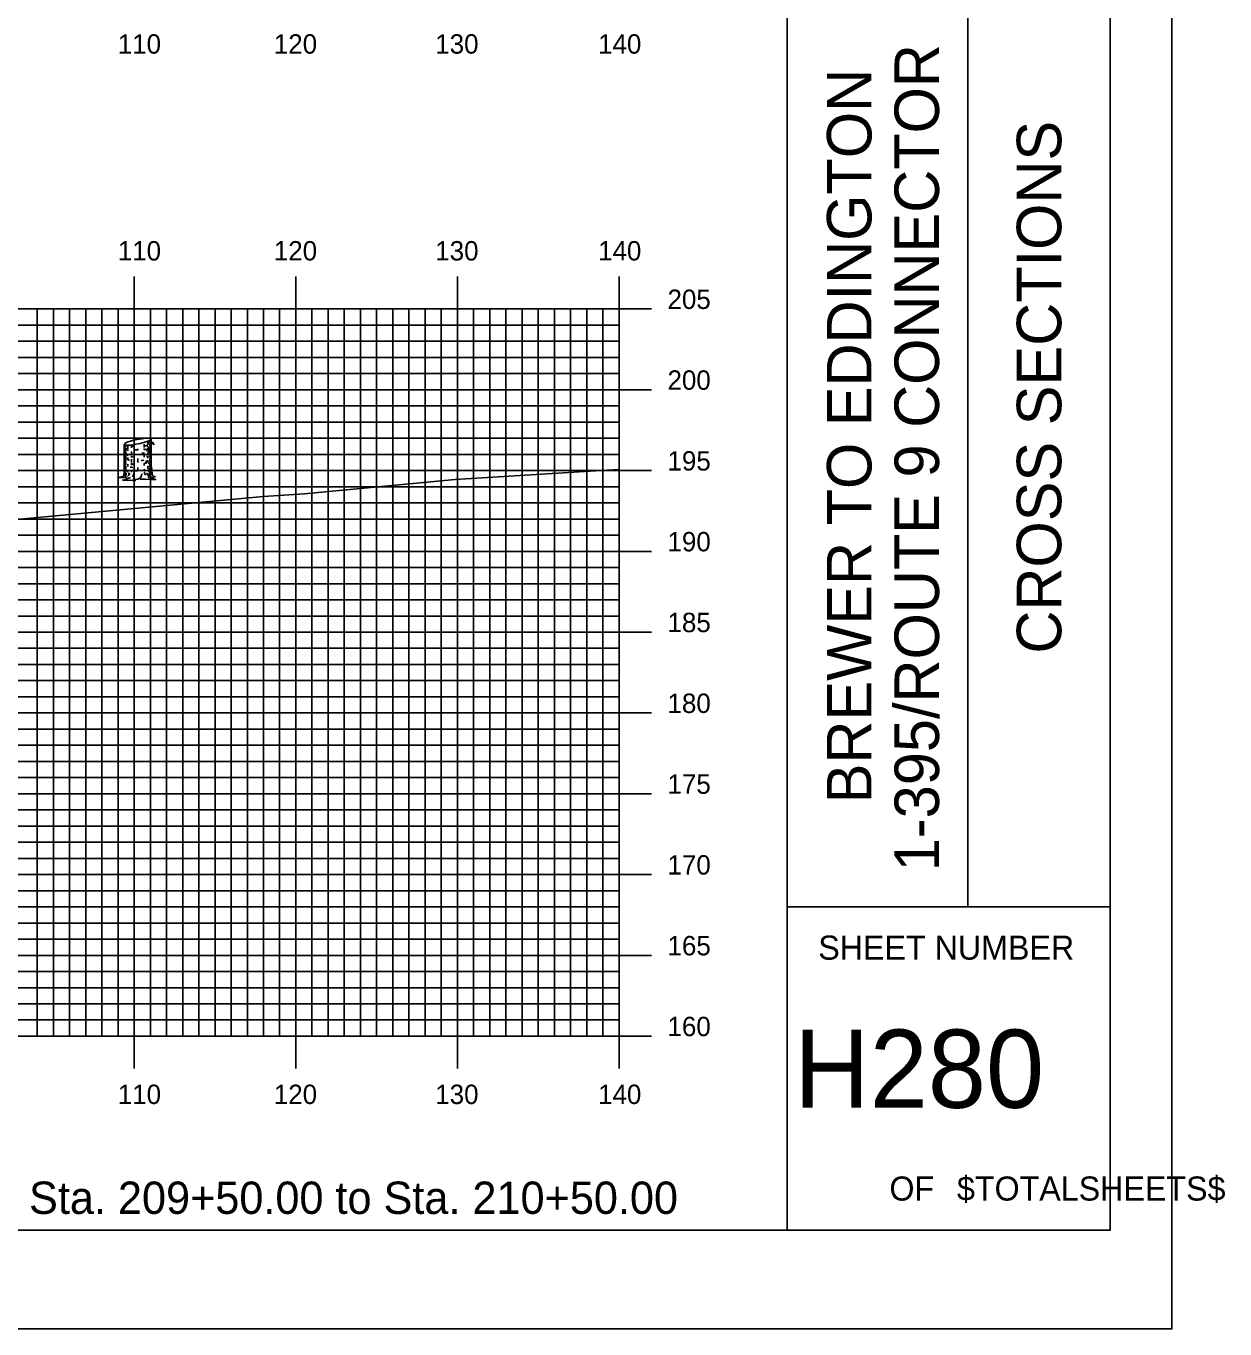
# Model space of a CAD drawing. Extents: x 1794453 to 1794796, y 442591 to 442811.
# Drawn here: x 1794721.6 to 1794795.8, y 442590.5 to 442671.2 of the extents above; entities that cross this region are included whole.
import ezdxf

# ---------------------------------------------------------------- set-up
doc = ezdxf.new("R2010")
doc.units = 0
for name, color, linetype in [('BORDER', 7, 'Continuous'), ('H_V ANNOTATION', 7, 'Continuous'), ('M_Trees_Conifer_Pay', 7, 'Continuous'), ('MAJOR', 7, 'Continuous'), ('MINOR', 7, 'Continuous'), ('PLOT BOUNDARY', 7, 'Continuous'), ('S_Roadway_Centerline', 7, 'Continuous')]:
    doc.layers.add(name, color=color, linetype=linetype)

msp = doc.modelspace()

# ---------------------------------------------------------------- linework, layer by layer
at = {"layer": 'BORDER'}
for p, q in [((1794768.74, 442596.665), (1794768.74, 442806.665)), ((1794779.922, 442616.671), (1794779.922, 442686.671)), ((1794768.74, 442616.671), (1794788.74, 442616.671))]:
    msp.add_line(p, q, dxfattribs=at)
msp.add_lwpolyline([(1794468.74, 442596.665), (1794788.74, 442596.665), (1794788.74, 442806.665), (1794468.74, 442806.665)], close=True, dxfattribs=at)
at = {"layer": 'M_Trees_Conifer_Pay'}
for p, q in [((1794729.19, 442645.486), (1794729.19, 442645.263)), ((1794729.308, 442645.547), (1794729.308, 442645.385)), ((1794729.379, 442643.973), (1794729.379, 442645.619)), ((1794727.715, 442643.562), (1794727.715, 442645.284)), ((1794727.762, 442645.247), (1794727.762, 442644.776)), ((1794727.762, 442644.711), (1794727.762, 442644.403)), ((1794727.821, 442645.236), (1794727.821, 442645.138)), ((1794727.821, 442645.064), (1794727.821, 442644.86)), ((1794727.821, 442644.802), (1794727.821, 442644.602)), ((1794727.946, 442645.228), (1794727.946, 442644.995)), ((1794727.946, 442644.955), (1794727.946, 442644.881)), ((1794728.166, 442645.248), (1794728.166, 442645.08)), ((1794728.166, 442644.843), (1794728.166, 442644.606)), ((1794728.572, 442645.016), (1794728.572, 442644.921)), ((1794728.962, 442645.29), (1794728.962, 442645.091)), ((1794728.962, 442645.033), (1794728.962, 442644.944)), ((1794728.962, 442644.597), (1794728.962, 442644.492)), ((1794729.19, 442645.175), (1794729.19, 442645.127)), ((1794729.19, 442644.792), (1794729.19, 442644.66)), ((1794729.247, 442644.992), (1794729.196, 442644.932)), ((1794729.308, 442645.317), (1794729.308, 442645.189)), ((1794729.308, 442645.002), (1794729.308, 442644.666)), ((1794729.308, 442644.629), (1794729.308, 442644.467)), ((1794727.762, 442644.356), (1794727.762, 442643.864)), ((1794727.762, 442643.81), (1794727.762, 442643.562)), ((1794727.821, 442644.555), (1794727.821, 442644.219)), ((1794727.821, 442644.166), (1794727.821, 442644.03)), ((1794727.821, 442643.931), (1794727.821, 442643.553)), ((1794727.946, 442644.477), (1794727.946, 442644.339)), ((1794727.946, 442644.067), (1794727.946, 442643.925)), ((1794728.166, 442644.362), (1794728.166, 442644.209)), ((1794728.166, 442644.166), (1794728.166, 442643.993)), ((1794728.572, 442644.403), (1794728.572, 442644.329)), ((1794728.572, 442644.304), (1794728.572, 442644.156)), ((1794728.572, 442643.864), (1794728.572, 442643.711)), ((1794728.962, 442644.125), (1794728.962, 442643.978)), ((1794729.19, 442644.549), (1794729.19, 442644.44)), ((1794729.19, 442644.304), (1794729.19, 442644.162)), ((1794729.19, 442643.935), (1794729.19, 442643.763)), ((1794729.308, 442644.419), (1794729.308, 442644.203)), ((1794729.308, 442644.172), (1794729.308, 442644.098)), ((1794729.308, 442644.057), (1794729.308, 442643.884)), ((1794727.946, 442643.663), (1794727.946, 442643.569)), ((1794727.946, 442643.169), (1794728.109, 442643.233)), ((1794728.166, 442643.715), (1794728.166, 442643.562)), ((1794728.383, 442643.105), (1794728.257, 442643.169)), ((1794728.962, 442643.746), (1794728.962, 442643.658))]:
    msp.add_line(p, q, dxfattribs=at)
for points in [[(1794729.196, 442645.118), (1794729.233, 442645.043), (1794729.28, 442645.1), (1794729.338, 442645.169), (1794729.43, 442645.362), (1794729.495, 442645.41), (1794729.526, 442645.416)], [(1794727.894, 442644.59), (1794727.888, 442644.685), (1794727.932, 442644.662), (1794727.932, 442644.568)], [(1794729.163, 442645.08), (1794729.132, 442644.995), (1794729.128, 442644.928), (1794729.159, 442644.864)], [(1794729.211, 442644.864), (1794729.247, 442644.992), (1794729.311, 442645.107), (1794729.342, 442645.175), (1794729.411, 442645.321)], [(1794729.425, 442645.35), (1794729.501, 442645.358), (1794729.573, 442645.259)], [(1794729.379, 442643.973), (1794729.43, 442643.711), (1794729.447, 442643.437), (1794729.505, 442643.312), (1794729.64, 442643.281), (1794729.41, 442643.244), (1794729.41, 442643.244), (1794729.416, 442643.196), (1794729.663, 442643.102), (1794729.389, 442643.118), (1794729.033, 442643.139), (1794728.712, 442643.128), (1794728.718, 442643.211), (1794728.57, 442643.128), (1794728.383, 442643.105), (1794728.407, 442643.037), (1794728.14, 442643.081), (1794727.919, 442643.054), (1794727.627, 442643.071), (1794727.915, 442643.128), (1794727.946, 442643.169), (1794727.783, 442643.227), (1794727.547, 442643.238), (1794727.306, 442643.238), (1794727.648, 442643.295), (1794727.689, 442643.375), (1794727.715, 442643.562)], [(1794729.033, 442644.191), (1794729.046, 442644.114), (1794729.093, 442644.125), (1794729.081, 442644.291)], [(1794729.305, 442643.83), (1794729.311, 442643.684), (1794729.358, 442643.616), (1794729.369, 442643.417)], [(1794727.763, 442643.515), (1794727.742, 442643.437), (1794727.722, 442643.343)], [(1794727.841, 442643.495), (1794727.847, 442643.379), (1794727.794, 442643.291), (1794727.783, 442643.227)], [(1794728.004, 442643.522), (1794728.004, 442643.39), (1794727.915, 442643.291)], [(1794728.23, 442643.281), (1794728.298, 442643.375), (1794728.325, 442643.515)], [(1794728.718, 442643.211), (1794728.793, 442643.352), (1794728.802, 442643.453)], [(1794728.969, 442643.579), (1794728.98, 442643.453), (1794729.054, 442643.41)], [(1794729.247, 442643.19), (1794729.233, 442643.328), (1794729.159, 442643.457)], [(1794729.206, 442643.684), (1794729.28, 442643.579), (1794729.285, 442643.406), (1794729.41, 442643.244)]]:
    msp.add_lwpolyline(points, dxfattribs=at)
for centre, radius, start, end in [((1794728.214, 442644.678), 0.802, 108.05939, 124.2194), ((1794729.571, 442640.517), 5.179, 101.7194, 108.05939), ((1794729.571, 442640.517), 5.179, 95.37941, 101.7194), ((1794727.524, 442650.387), 5.179, 281.7194, 288.05939), ((1794729.161, 442644.875), 0.802, 79.2194, 95.37941), ((1794728.881, 442646.225), 0.802, 288.05939, 304.2194), ((1794729.048, 442645.933), 0.571, 284.43166, 292.41325), ((1794729.264, 442645.416), 0.251, 71.05013, 79.2194), ((1794729.19, 442645.77), 0.251, 304.2194, 312.38868), ((1794729.248, 442645.588), 0.172, 300, 311.25059), ((1794729.319, 442645.576), 0.0817, 56.7194, 71.05013), ((1794729.304, 442645.645), 0.0817, 312.38868, 326.7194), ((1794729.32, 442645.505), 0.0624, 311.25059, 330), ((1794729.335, 442645.6), 0.0527, 46.92298, 56.7194), ((1794729.349, 442645.615), 0.0314, 34.2194, 46.92298), ((1794729.328, 442645.629), 0.0527, 326.7194, 336.51582), ((1794729.336, 442645.496), 0.0441, 330, 343.94846), ((1794729.353, 442645.618), 0.0264, 23.40735, 34.2194), ((1794729.357, 442645.62), 0.0226, 11.7194, 23.40735), ((1794729.348, 442645.621), 0.0314, 336.51582, 349.2194), ((1794729.346, 442645.493), 0.0334, 343.94846, 354.21506), ((1794729.357, 442645.62), 0.0226, 0.03145, 11.7194), ((1794729.353, 442645.62), 0.0264, 349.2194, 0.03145), ((1794727.747, 442645.106), 0.0334, 163.94846, 180), ((1794727.747, 442645.106), 0.0334, 180, 196.05154), ((1794727.747, 442644.659), 0.0334, 163.94846, 180), ((1794727.747, 442644.659), 0.0334, 180, 196.05154), ((1794727.742, 442645.284), 0.0264, 169.2194, 180.03145), ((1794727.738, 442645.284), 0.0226, 180.03145, 191.7194), ((1794727.758, 442645.109), 0.0441, 196.05154, 210), ((1794727.758, 442644.662), 0.0441, 196.05154, 210), ((1794727.747, 442645.283), 0.0314, 156.51582, 169.2194), ((1794727.738, 442645.284), 0.0226, 191.7194, 203.40735), ((1794727.741, 442645.285), 0.0264, 203.40735, 214.2194), ((1794727.766, 442645.274), 0.0527, 146.7194, 156.51582), ((1794727.746, 442645.288), 0.0314, 214.2194, 226.92298), ((1794727.774, 442645.118), 0.0624, 210, 228.74941), ((1794727.774, 442644.671), 0.0624, 210, 228.74941), ((1794727.79, 442645.259), 0.0817, 132.38868, 146.7194), ((1794727.76, 442645.304), 0.0527, 226.92298, 236.7194), ((1794727.776, 442645.328), 0.0817, 236.7194, 251.05013), ((1794727.846, 442645.201), 0.172, 228.74941, 240), ((1794727.846, 442644.754), 0.172, 228.74941, 240), ((1794727.904, 442645.134), 0.251, 124.2194, 132.38868), ((1794727.831, 442645.488), 0.251, 251.05013, 259.2194), ((1794728.045, 442645.546), 0.571, 240, 240.33672), ((1794728.045, 442645.099), 0.571, 240, 240.33672), ((1794728.047, 442645.335), 0.571, 240, 247.05866), ((1794727.934, 442646.029), 0.802, 259.2194, 275.37941), ((1794728.045, 442645.546), 0.571, 246.85973, 257.98457), ((1794727.524, 442650.387), 5.179, 275.37941, 281.7194), ((1794728.547, 442649.296), 4.124, 264.6955, 266.73309), ((1794728.546, 442649.063), 4.124, 268.07512, 270), ((1794728.546, 442649.063), 4.124, 270, 270.35814), ((1794728.547, 442648.852), 4.124, 273.70524, 275.95043), ((1794728.546, 442649.063), 4.124, 275.78493, 277.05584), ((1794728.547, 442649.296), 4.124, 276.23804, 278.1032), ((1794729.048, 442645.779), 0.571, 278.1032, 284.36665), ((1794729.048, 442645.335), 0.571, 284.44928, 297.04285), ((1794729.048, 442645.779), 0.571, 297.0237, 300), ((1794729.047, 442645.099), 0.571, 297.18959, 300), ((1794729.246, 442644.754), 0.172, 300, 311.25059), ((1794729.248, 442645.434), 0.172, 300, 311.25059), ((1794729.319, 442644.671), 0.0624, 311.25059, 330), ((1794729.32, 442645.351), 0.0624, 311.25059, 330), ((1794729.334, 442644.662), 0.0441, 330, 343.94846), ((1794729.336, 442645.342), 0.0441, 330, 343.94846), ((1794729.345, 442644.659), 0.0334, 343.94846, 354.21506), ((1794729.346, 442645.339), 0.0334, 343.94846, 354.21506), ((1794729.346, 442644.895), 0.0334, 343.94846, 354.21506), ((1794727.747, 442644.449), 0.0334, 163.94846, 180), ((1794727.747, 442644.449), 0.0334, 180, 196.05154), ((1794727.747, 442644.212), 0.0334, 163.94846, 180), ((1794727.747, 442644.212), 0.0334, 180, 196.05154), ((1794727.747, 442644.015), 0.0334, 163.94846, 180), ((1794727.747, 442643.819), 0.0334, 163.94846, 180), ((1794727.747, 442643.819), 0.0334, 180, 196.05154), ((1794727.758, 442644.452), 0.0441, 196.05154, 210), ((1794727.758, 442644.215), 0.0441, 196.05154, 210), ((1794727.758, 442643.822), 0.0441, 196.05154, 210), ((1794727.774, 442644.461), 0.0624, 210, 228.74941), ((1794727.774, 442644.224), 0.0624, 210, 228.74941), ((1794727.774, 442643.831), 0.0624, 210, 228.74941), ((1794727.846, 442644.544), 0.172, 228.74941, 240), ((1794727.846, 442644.307), 0.172, 228.74941, 240), ((1794728.045, 442644.889), 0.571, 240, 246.85973), ((1794728.045, 442644.652), 0.571, 240, 246.85973), ((1794728.034, 442644.461), 0.571, 241.23686, 248.02677), ((1794728.045, 442644.889), 0.571, 259.27072, 261.8968), ((1794728.546, 442648.406), 4.124, 261.8968, 263.14738), ((1794728.546, 442647.972), 4.124, 263.49906, 265.83975), ((1794728.546, 442648.616), 4.124, 264.08098, 266.66759), ((1794728.546, 442648.17), 4.124, 264.71603, 266.31934), ((1794728.546, 442648.406), 4.124, 270, 270.35814), ((1794728.546, 442648.406), 4.124, 273.14934, 275.45691), ((1794728.546, 442648.616), 4.124, 277.61247, 278.1032), ((1794729.047, 442645.099), 0.571, 278.1032, 286.92962), ((1794729.047, 442644.652), 0.571, 285.39827, 297.18959), ((1794729.047, 442644.454), 0.571, 289.29072, 300), ((1794729.047, 442644.889), 0.571, 297.18959, 300), ((1794729.246, 442644.544), 0.172, 300, 311.25059), ((1794729.246, 442644.109), 0.172, 300, 311.25059), ((1794729.319, 442644.461), 0.0624, 311.25059, 330), ((1794729.319, 442644.027), 0.0624, 311.25059, 330), ((1794729.334, 442644.452), 0.0441, 330, 343.94846), ((1794729.334, 442644.018), 0.0441, 330, 343.94846), ((1794729.345, 442644.449), 0.0334, 343.94846, 354.21506), ((1794729.345, 442644.015), 0.0334, 343.94846, 354.21506), ((1794727.747, 442643.599), 0.0334, 163.94846, 180), ((1794727.747, 442643.599), 0.0334, 180, 196.05154), ((1794727.758, 442643.602), 0.0441, 196.05154, 210), ((1794727.774, 442643.611), 0.0624, 210, 228.74941), ((1794727.846, 442643.914), 0.172, 228.74941, 240), ((1794727.846, 442643.693), 0.172, 228.74941, 240), ((1794728.045, 442644.259), 0.571, 240, 246.85973), ((1794728.045, 442644.039), 0.571, 240, 244.53138), ((1794728.546, 442647.556), 4.124, 262.44379, 263.51202), ((1794728.546, 442647.776), 4.124, 267.81166, 270), ((1794728.546, 442647.776), 4.124, 270, 270.13279), ((1794728.546, 442647.776), 4.124, 275.78493, 276.78961), ((1794728.546, 442647.556), 4.124, 277.36842, 278.1032), ((1794729.047, 442644.039), 0.571, 278.1032, 281.63703), ((1794729.047, 442644.259), 0.571, 288.50673, 297.27208), ((1794729.246, 442643.693), 0.172, 300, 311.25059), ((1794729.319, 442643.611), 0.0624, 311.25059, 330), ((1794729.334, 442643.602), 0.0441, 330, 343.94846), ((1794729.345, 442643.599), 0.0334, 343.94846, 354.21506)]:
    msp.add_arc(centre, radius, start, end, dxfattribs=at)
at = {"layer": 'MAJOR'}
for p, q in [((1794728.34, 442655.669), (1794728.34, 442653.665)), ((1794738.34, 442655.669), (1794738.34, 442653.665)), ((1794748.34, 442655.669), (1794748.34, 442653.665)), ((1794758.34, 442655.669), (1794758.34, 442653.665)), ((1794478.34, 442653.665), (1794758.34, 442653.665)), ((1794478.34, 442653.665), (1794758.34, 442653.665)), ((1794728.34, 442608.665), (1794728.34, 442653.665)), ((1794738.34, 442608.665), (1794738.34, 442653.665)), ((1794748.34, 442608.665), (1794748.34, 442653.665)), ((1794760.344, 442653.665), (1794756.336, 442653.665)), ((1794758.34, 442608.665), (1794758.34, 442653.665)), ((1794758.34, 442608.665), (1794758.34, 442653.665)), ((1794478.34, 442648.665), (1794758.34, 442648.665)), ((1794760.344, 442648.665), (1794756.336, 442648.665)), ((1794478.34, 442643.665), (1794758.34, 442643.665)), ((1794760.344, 442643.665), (1794756.336, 442643.665)), ((1794478.34, 442638.665), (1794758.34, 442638.665)), ((1794760.344, 442638.665), (1794756.336, 442638.665)), ((1794478.34, 442633.665), (1794758.34, 442633.665)), ((1794760.344, 442633.665), (1794756.336, 442633.665)), ((1794478.34, 442628.665), (1794758.34, 442628.665)), ((1794760.344, 442628.665), (1794756.336, 442628.665)), ((1794478.34, 442623.665), (1794758.34, 442623.665)), ((1794760.344, 442623.665), (1794756.336, 442623.665)), ((1794478.34, 442618.665), (1794758.34, 442618.665)), ((1794760.344, 442618.665), (1794756.336, 442618.665)), ((1794478.34, 442613.665), (1794758.34, 442613.665)), ((1794760.344, 442613.665), (1794756.336, 442613.665)), ((1794478.34, 442608.665), (1794758.34, 442608.665)), ((1794478.34, 442608.665), (1794758.34, 442608.665)), ((1794728.34, 442606.661), (1794728.34, 442608.665)), ((1794738.34, 442606.661), (1794738.34, 442608.665)), ((1794748.34, 442606.661), (1794748.34, 442608.665)), ((1794760.344, 442608.665), (1794756.336, 442608.665)), ((1794758.34, 442606.661), (1794758.34, 442608.665))]:
    msp.add_line(p, q, dxfattribs=at)
at = {"layer": 'MINOR'}
for p, q in [((1794722.34, 442608.665), (1794722.34, 442653.665)), ((1794723.34, 442608.665), (1794723.34, 442653.665)), ((1794724.34, 442608.665), (1794724.34, 442653.665)), ((1794725.34, 442608.665), (1794725.34, 442653.665)), ((1794726.34, 442608.665), (1794726.34, 442653.665)), ((1794727.34, 442608.665), (1794727.34, 442653.665)), ((1794729.34, 442608.665), (1794729.34, 442653.665)), ((1794730.34, 442608.665), (1794730.34, 442653.665)), ((1794731.34, 442608.665), (1794731.34, 442653.665)), ((1794732.34, 442608.665), (1794732.34, 442653.665)), ((1794733.34, 442608.665), (1794733.34, 442653.665)), ((1794734.34, 442608.665), (1794734.34, 442653.665)), ((1794735.34, 442608.665), (1794735.34, 442653.665)), ((1794736.34, 442608.665), (1794736.34, 442653.665)), ((1794737.34, 442608.665), (1794737.34, 442653.665)), ((1794739.34, 442608.665), (1794739.34, 442653.665)), ((1794740.34, 442608.665), (1794740.34, 442653.665)), ((1794741.34, 442608.665), (1794741.34, 442653.665)), ((1794742.34, 442608.665), (1794742.34, 442653.665)), ((1794743.34, 442608.665), (1794743.34, 442653.665)), ((1794744.34, 442608.665), (1794744.34, 442653.665)), ((1794745.34, 442608.665), (1794745.34, 442653.665)), ((1794746.34, 442608.665), (1794746.34, 442653.665)), ((1794747.34, 442608.665), (1794747.34, 442653.665)), ((1794749.34, 442608.665), (1794749.34, 442653.665)), ((1794750.34, 442608.665), (1794750.34, 442653.665)), ((1794751.34, 442608.665), (1794751.34, 442653.665)), ((1794752.34, 442608.665), (1794752.34, 442653.665)), ((1794753.34, 442608.665), (1794753.34, 442653.665)), ((1794754.34, 442608.665), (1794754.34, 442653.665)), ((1794755.34, 442608.665), (1794755.34, 442653.665)), ((1794756.34, 442608.665), (1794756.34, 442653.665)), ((1794757.34, 442608.665), (1794757.34, 442653.665)), ((1794478.34, 442652.665), (1794758.34, 442652.665)), ((1794758.34, 442652.665), (1794756.336, 442652.665)), ((1794478.34, 442651.665), (1794758.34, 442651.665)), ((1794758.34, 442651.665), (1794756.336, 442651.665)), ((1794478.34, 442650.665), (1794758.34, 442650.665)), ((1794758.34, 442650.665), (1794756.336, 442650.665)), ((1794478.34, 442649.665), (1794758.34, 442649.665)), ((1794758.34, 442649.665), (1794756.336, 442649.665)), ((1794478.34, 442647.665), (1794758.34, 442647.665)), ((1794758.34, 442647.665), (1794756.336, 442647.665)), ((1794478.34, 442646.665), (1794758.34, 442646.665)), ((1794758.34, 442646.665), (1794756.336, 442646.665)), ((1794478.34, 442645.665), (1794758.34, 442645.665)), ((1794758.34, 442645.665), (1794756.336, 442645.665)), ((1794478.34, 442644.665), (1794758.34, 442644.665)), ((1794758.34, 442644.665), (1794756.336, 442644.665)), ((1794478.34, 442642.665), (1794758.34, 442642.665)), ((1794758.34, 442642.665), (1794756.336, 442642.665)), ((1794478.34, 442641.665), (1794758.34, 442641.665)), ((1794758.34, 442641.665), (1794756.336, 442641.665)), ((1794478.34, 442640.665), (1794758.34, 442640.665)), ((1794758.34, 442640.665), (1794756.336, 442640.665)), ((1794478.34, 442639.665), (1794758.34, 442639.665)), ((1794758.34, 442639.665), (1794756.336, 442639.665)), ((1794478.34, 442637.665), (1794758.34, 442637.665)), ((1794758.34, 442637.665), (1794756.336, 442637.665)), ((1794478.34, 442636.665), (1794758.34, 442636.665)), ((1794758.34, 442636.665), (1794756.336, 442636.665)), ((1794478.34, 442635.665), (1794758.34, 442635.665)), ((1794758.34, 442635.665), (1794756.336, 442635.665)), ((1794478.34, 442634.665), (1794758.34, 442634.665)), ((1794758.34, 442634.665), (1794756.336, 442634.665)), ((1794478.34, 442632.665), (1794758.34, 442632.665)), ((1794758.34, 442632.665), (1794756.336, 442632.665)), ((1794478.34, 442631.665), (1794758.34, 442631.665)), ((1794758.34, 442631.665), (1794756.336, 442631.665)), ((1794478.34, 442630.665), (1794758.34, 442630.665)), ((1794758.34, 442630.665), (1794756.336, 442630.665)), ((1794478.34, 442629.665), (1794758.34, 442629.665)), ((1794758.34, 442629.665), (1794756.336, 442629.665)), ((1794478.34, 442627.665), (1794758.34, 442627.665)), ((1794758.34, 442627.665), (1794756.336, 442627.665)), ((1794478.34, 442626.665), (1794758.34, 442626.665)), ((1794758.34, 442626.665), (1794756.336, 442626.665)), ((1794478.34, 442625.665), (1794758.34, 442625.665)), ((1794758.34, 442625.665), (1794756.336, 442625.665)), ((1794478.34, 442624.665), (1794758.34, 442624.665)), ((1794758.34, 442624.665), (1794756.336, 442624.665)), ((1794478.34, 442622.665), (1794758.34, 442622.665)), ((1794758.34, 442622.665), (1794756.336, 442622.665)), ((1794478.34, 442621.665), (1794758.34, 442621.665)), ((1794758.34, 442621.665), (1794756.336, 442621.665)), ((1794478.34, 442620.665), (1794758.34, 442620.665)), ((1794758.34, 442620.665), (1794756.336, 442620.665)), ((1794478.34, 442619.665), (1794758.34, 442619.665)), ((1794758.34, 442619.665), (1794756.336, 442619.665)), ((1794478.34, 442617.665), (1794758.34, 442617.665)), ((1794758.34, 442617.665), (1794756.336, 442617.665)), ((1794478.34, 442616.665), (1794758.34, 442616.665)), ((1794758.34, 442616.665), (1794756.336, 442616.665)), ((1794478.34, 442615.665), (1794758.34, 442615.665)), ((1794758.34, 442615.665), (1794756.336, 442615.665)), ((1794478.34, 442614.665), (1794758.34, 442614.665)), ((1794758.34, 442614.665), (1794756.336, 442614.665)), ((1794478.34, 442612.665), (1794758.34, 442612.665)), ((1794758.34, 442612.665), (1794756.336, 442612.665)), ((1794478.34, 442611.665), (1794758.34, 442611.665)), ((1794758.34, 442611.665), (1794756.336, 442611.665)), ((1794478.34, 442610.665), (1794758.34, 442610.665)), ((1794758.34, 442610.665), (1794756.336, 442610.665)), ((1794478.34, 442609.665), (1794758.34, 442609.665)), ((1794758.34, 442609.665), (1794756.336, 442609.665))]:
    msp.add_line(p, q, dxfattribs=at)
at = {"layer": 'PLOT BOUNDARY'}
msp.add_lwpolyline([(1794452.553, 442590.547), (1794792.553, 442590.547), (1794792.553, 442810.547), (1794452.553, 442810.547)], close=True, dxfattribs=at)
at = {"layer": 'S_Roadway_Centerline'}
msp.add_lwpolyline([(1794663.047, 442639.173), (1794664.443, 442639.315), (1794669.598, 442638.545), (1794671.135, 442638.442), (1794677.411, 442638.642), (1794681.849, 442638.451), (1794698.305, 442639.412), (1794700.928, 442639.577), (1794712.523, 442640.051), (1794721.041, 442640.627), (1794736.343, 442642.062), (1794738.863, 442642.231), (1794748.21, 442643.105), (1794757.223, 442643.674), (1794758.34, 442643.741)], dxfattribs=at)

# ---------------------------------------------------------------- texts
at = {"layer": 'BORDER'}
for s, p in [('1-395/ROUTE 9 CONNECTOR', (1794778.143, 442618.865)), ('BREWER TO EDDINGTON', (1794773.963, 442623.074)), ('CROSS SECTIONS', (1794785.709, 442632.339))]:
    msp.add_text(s, height=2.75575, rotation=90, dxfattribs=at).set_placement(p)
for s, height, p in [('SHEET NUMBER', 1.49054, (1794770.671, 442613.398)), ('H280', 4.8388, (1794769.179, 442604.23)), ('OF', 1.4905, (1794775.074, 442598.491)), ('$TOTALSHEETS$', 1.49054, (1794779.253, 442598.491))]:
    msp.add_text(s, height=height, dxfattribs=at).set_placement(p)
at = {"layer": 'H_V ANNOTATION'}
for s, height, p in [('110', 1.2, (1794727.323, 442669.465)), ('120', 1.2, (1794736.98, 442669.465)), ('130', 1.2, (1794746.97, 442669.465)), ('140', 1.2, (1794757.045, 442669.465)), ('110', 1.2, (1794727.323, 442656.665)), ('120', 1.2, (1794736.98, 442656.665)), ('130', 1.2, (1794746.97, 442656.665)), ('140', 1.2, (1794757.045, 442656.665)), ('205', 1.2, (1794761.34, 442653.665)), ('200', 1.2, (1794761.34, 442648.665)), ('195', 1.2, (1794761.34, 442643.665)), ('190', 1.2, (1794761.34, 442638.665)), ('185', 1.2, (1794761.34, 442633.665)), ('180', 1.2, (1794761.34, 442628.665)), ('175', 1.2, (1794761.34, 442623.665)), ('170', 1.2, (1794761.34, 442618.665)), ('165', 1.2, (1794761.34, 442613.665)), ('160', 1.2, (1794761.34, 442608.665)), ('110', 1.2, (1794727.323, 442604.465)), ('120', 1.2, (1794736.98, 442604.465)), ('130', 1.2, (1794746.97, 442604.465)), ('140', 1.2, (1794757.045, 442604.465)), ('Sta. 209+50.00 to Sta. 210+50.00', 2.0004, (1794721.831, 442597.665))]:
    msp.add_text(s, height=height, dxfattribs=at).set_placement(p)

doc.saveas('drawing.dxf')
